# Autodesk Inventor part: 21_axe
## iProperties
Created: 2002-11
Part Number: 21_axe
Material: Par défaut
Document SubType Name: Modélisation
Designer: FIEVET
Control State: 0
Master: False
Checked Out: False
Shininess: 77.0
Length Units: 11269
Angle Units: 11279
Time Units: 11290
Mass Units: 11283
Length Display Precision: 3
Angle Display Precision: 2
Compacted: True
Density: 0.0
Volumn: 0.0
Area: 0.0
PropertySet Name: Model Information
Author: FIEVET
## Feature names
1. Révolution1 [Revolution]
